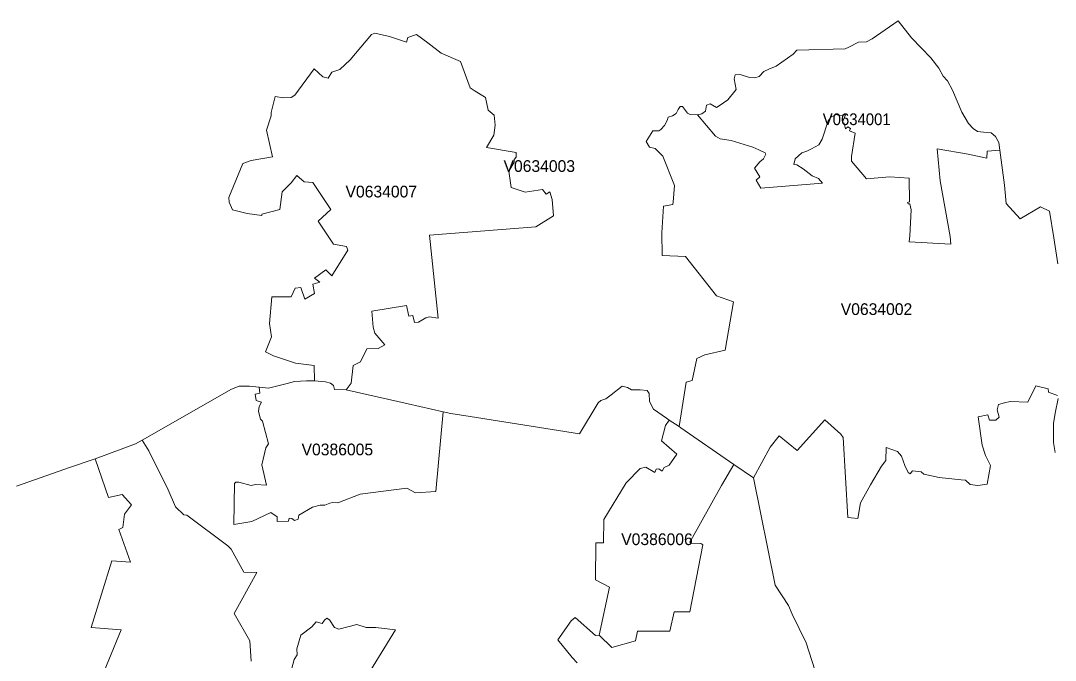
# Model space of a CAD drawing. Extents: x 369010 to 735936, y 6377141 to 6616555.
# Drawn here: x 440462 to 449282, y 6481136 to 6486588 of the extents above; entities that cross this region are included whole.
import ezdxf
from ezdxf.enums import TextEntityAlignment as Align

# ---------------------------------------------------------------- set-up
doc = ezdxf.new("R2010")
doc.units = 0
doc.header["$LTSCALE"] = 40
doc.layers.add('3', color=7, linetype='Continuous', lineweight=13)
doc.layers.add('4', color=7, linetype='Continuous')

msp = doc.modelspace()

# ---------------------------------------------------------------- linework, layer by layer
at = {"layer": '3'}
for points in [[(443297.34, 6483648.44), (443279.3, 6483498.16), (443236.1, 6483442.55), (443766.54, 6483322.39), (444063.79, 6483254.54), (444128.17, 6483239.81), (444294.33, 6483212.67), (445224.47, 6483065.7), (445385.67, 6483329.35), (445407.02, 6483350.36), (445451.37, 6483365.43), (445495.56, 6483399.02), (445590.23, 6483472.67), (445634.75, 6483462.41), (445670.33, 6483441.39), (445741.67, 6483442.72), (445803.4, 6483435.43), (445818.46, 6483409.45), (445823.92, 6483342.09), (445857.85, 6483275.89), (445966.59, 6483199.09), (445990.42, 6483183.37), (446074.33, 6483127.93), (446134.41, 6483507.26), (446186.04, 6483520.17), (446224.94, 6483709.34), (446293.46, 6483740.46), (446468.06, 6483779.19), (446537.41, 6484190.79), (446393.75, 6484241.27), (446129.77, 6484576.91), (445930.51, 6484587.34), (445927.2, 6484779.33), (445941.26, 6485008.05), (446020.71, 6485020.96), (446023.19, 6485040.16), (446034.77, 6485183.82), (445936.3, 6485432.24), (445869.77, 6485498.94), (445822.27, 6485509.2), (445794.13, 6485559.18), (445852.06, 6485649.55), (445900.88, 6485648.22), (445920.08, 6485659.81), (445950.86, 6485695.56), (445973.87, 6485736.6), (445982.81, 6485766.23), (446018.72, 6485776.49), (446049.5, 6485798.17), (446066.22, 6485831.6), (446082.77, 6485857.25), (446103.29, 6485855.93), (446146.82, 6485799.49), (446169.99, 6485787.91), (446231.39, 6485785.76), (446269.79, 6485793.53), (446299.25, 6485817.86), (446309.51, 6485866.52), (446338.97, 6485878.11), (446392.76, 6485848.65), (446417.25, 6485861.39), (446491.56, 6485912.7), (446562.4, 6486002.24), (446543.04, 6486091.94), (446552.14, 6486127.85), (446595.67, 6486130.5), (446676.43, 6486103.52), (446721.28, 6486101.04), (446757.2, 6486112.46), (446798.08, 6486156.15), (446840.45, 6486175.35), (446902.01, 6486199.68), (447047.99, 6486301.96), (447079.93, 6486336.55), (447491.37, 6486349.46), (447521.17, 6486361.05), (447604.58, 6486405.9), (447673.76, 6486408.55), (447719.94, 6486434.04), (447941.55, 6486587.95), (448055.41, 6486442.48), (448220.75, 6486272.01), (448289.93, 6486183.46), (448324.69, 6486114.78), (448361.93, 6486075.06), (448406.78, 6485995.62), (448484.89, 6485809.59), (448541.33, 6485710.95), (448582.54, 6485667.59), (448618.46, 6485643.09), (448670.92, 6485636.8), (448734.97, 6485631.67), (448770.89, 6485602.05), (448800.35, 6485549.58), (448808.12, 6485482.88), (448849.17, 6485186.47), (448862.24, 6485029.73), (448981.41, 6484898.99), (449156.18, 6485001.76), (449231.98, 6484964.53)], [(442965.34, 6483519.18), (443059.18, 6483509.08), (443104.36, 6483498.33), (443128.03, 6483477.64), (443135.81, 6483443.71), (443236.1, 6483442.55), (443279.3, 6483498.16), (443297.34, 6483648.44), (443357.91, 6483680.88), (443413.52, 6483789.61), (443508.02, 6483794.74), (443564.96, 6483824.53), (443482.04, 6483924.17), (443467.81, 6483974.65), (443454.24, 6484111.68), (443750.49, 6484159.68), (443769.85, 6484068.98), (443804.77, 6484075.44), (443819.01, 6484016.02), (443852.27, 6484017.35), (443915.66, 6484054.92), (443942.8, 6484062.69), (444020.42, 6484052.27), (443946.61, 6484760.96), (444853.24, 6484829.64), (445004.68, 6484924.14), (444992.93, 6485063.83), (444972.57, 6485128.54), (444941.45, 6485109.01), (444911.66, 6485147.9), (444762.88, 6485127.22), (444643.88, 6485167.27), (444623.19, 6485304.47), (444668.54, 6485380.93), (444668.54, 6485405.43), (444686.58, 6485423.63), (444686.58, 6485463.69), (444434.18, 6485508.37), (444496.25, 6485613.14), (444508, 6485697.38), (444497.57, 6485781.45), (444447.26, 6485825.97), (444423.92, 6485932.23), (444328.26, 6485991.64), (444294.5, 6486016.3), (444211.75, 6486240.23), (444047.73, 6486310.9), (443932.54, 6486400.11), (443836.88, 6486471.27), (443761.74, 6486445.45), (443751.48, 6486405.24), (443606.66, 6486451.91), (443479.89, 6486480.38), (443451.42, 6486471.27), (443270.2, 6486255.29), (443183.47, 6486172.37), (443114.95, 6486149.2), (443084, 6486097.4), (443038.65, 6486110.31), (442962.36, 6486176.35), (442797.85, 6485953.91), (442766.73, 6485934.54), (442702.02, 6485929.25), (442632.18, 6485941), (442597.75, 6485805.29), (442597.75, 6485776.82), (442556.38, 6485653.85), (442608.18, 6485426.12), (442425.79, 6485396.33), (442354.63, 6485370.51), (442236.46, 6485081.7), (442237.78, 6485041.48), (442268.9, 6484975.61), (442391.7, 6484944.5), (442517.15, 6484926.29), (442518.48, 6484938.04), (442669.91, 6484979.42), (442691.92, 6485128.71), (442768.22, 6485205), (442817.38, 6485269.71), (442879.44, 6485215.43), (442951.93, 6485207.65), (443105.85, 6484978.43), (442998.6, 6484880.12), (443128.36, 6484683.66), (443239.58, 6484662.98), (443251.33, 6484630.54), (443115.45, 6484414.39), (443063.65, 6484464.87), (442967.98, 6484392.38), (443013.17, 6484360.1), (442952.1, 6484342.06), (442966.33, 6484261.8), (442883.58, 6484213.96), (442849.98, 6484314.92), (442800.83, 6484308.47), (442768.55, 6484234.65), (442601.56, 6484233.33), (442582.69, 6484007.91), (442600.73, 6483892.72)], [(442795.03, 6483512.39), (442898.47, 6483518.85), (442965.34, 6483519.18), (442962.52, 6483648.6), (442805.96, 6483669.29), (442618.44, 6483731.35), (442550.25, 6483765.95), (442600.73, 6483892.72), (442582.69, 6484007.91), (442601.56, 6484233.33), (442768.55, 6484234.65), (442800.83, 6484308.47), (442849.98, 6484314.92), (442883.58, 6484213.96), (442966.33, 6484261.8), (442952.1, 6484342.06), (443013.17, 6484360.1), (442967.98, 6484392.38), (443063.65, 6484464.87), (443115.45, 6484414.39), (443251.33, 6484630.54), (443239.58, 6484662.98), (443128.36, 6484683.66), (442998.6, 6484880.12), (443105.85, 6484978.43), (442951.93, 6485207.65), (442879.44, 6485215.43), (442817.38, 6485269.71), (442768.22, 6485205), (442691.92, 6485128.71), (442669.91, 6484979.42), (442518.48, 6484938.04), (442517.15, 6484926.29), (442391.7, 6484944.5), (442268.9, 6484975.61), (442237.78, 6485041.48), (442236.46, 6485081.7), (442354.63, 6485370.51), (442425.79, 6485396.33), (442608.18, 6485426.12), (442556.38, 6485653.85), (442597.75, 6485776.82), (442597.75, 6485805.29), (442632.18, 6485941), (442702.02, 6485929.25), (442766.73, 6485934.54), (442797.85, 6485953.91), (442962.36, 6486176.35), (443038.65, 6486110.31), (443084, 6486097.4), (443114.95, 6486149.2), (443183.47, 6486172.37), (443270.2, 6486255.29), (443451.42, 6486471.27), (443479.89, 6486480.38), (443606.66, 6486451.91), (443751.48, 6486405.24), (443761.74, 6486445.45), (443836.88, 6486471.27), (443932.54, 6486400.11), (444047.73, 6486310.9), (444211.75, 6486240.23), (444294.5, 6486016.3), (444328.26, 6485991.64), (444423.92, 6485932.23), (444447.26, 6485825.97), (444497.57, 6485781.45), (444508, 6485697.38), (444496.25, 6485613.14), (444434.18, 6485508.37), (444686.58, 6485463.69), (444686.58, 6485423.63), (444668.54, 6485405.43), (444668.54, 6485380.93), (444623.19, 6485304.47), (444643.88, 6485167.27), (444762.88, 6485127.22), (444911.66, 6485147.9), (444941.45, 6485109.01), (444972.57, 6485128.54), (444992.93, 6485063.83), (445004.68, 6484924.14), (444853.24, 6484829.64), (443946.61, 6484760.96), (444020.42, 6484052.27), (443942.8, 6484062.69), (443915.66, 6484054.92), (443852.27, 6484017.35), (443819.01, 6484016.02), (443804.77, 6484075.44), (443769.85, 6484068.98), (443750.49, 6484159.68), (443454.24, 6484111.68), (443467.81, 6483974.65), (443482.04, 6483924.17), (443564.96, 6483824.53), (443508.02, 6483794.74), (443413.52, 6483789.61), (443357.91, 6483680.88), (443297.34, 6483648.44)], [(448042.67, 6485025.76), (448027.28, 6485025.76), (448022.15, 6485037.35), (448040.02, 6485043.8), (448034.89, 6485245.05), (447872.2, 6485256.64), (447673.43, 6485238.6), (447544.67, 6485390.04), (447545.99, 6485429.76), (447575.45, 6485629.85), (447526.79, 6485647.73), (447535.73, 6485669.57), (447512.72, 6485682.48), (447494.68, 6485667.09), (447481.94, 6485710.62), (447466.55, 6485723.53), (447492.2, 6485786.25), (447437.09, 6485779.8), (447417.89, 6485787.58), (447370.39, 6485767.05), (447346.06, 6485734.95), (447294.76, 6485577.22), (447265.3, 6485531.05), (447204.23, 6485496.46), (447164.5, 6485477.09), (447120.81, 6485461.7), (447064.54, 6485409.23), (447051.63, 6485363.06), (447077.28, 6485357.93), (447132.4, 6485325.82), (447210.68, 6485266.9), (447263.14, 6485243.73), (447297.73, 6485204.01), (446770.77, 6485161.64), (446731.05, 6485229.66), (446764.48, 6485257.96), (446716.98, 6485329.79), (446764.48, 6485384.91), (446795.26, 6485409.23), (446815.62, 6485448.96), (446809.33, 6485461.86), (446754.22, 6485487.52), (446702.91, 6485509.2), (446519.7, 6485566.96), (446426.03, 6485581.03), (446383.82, 6485603.7), (446231.39, 6485785.76), (446169.99, 6485787.91), (446146.82, 6485799.49), (446103.29, 6485855.93), (446082.77, 6485857.25), (446066.22, 6485831.6), (446049.5, 6485798.17), (446018.72, 6485776.49), (445982.81, 6485766.23), (445973.87, 6485736.6), (445950.86, 6485695.56), (445920.08, 6485659.81), (445900.88, 6485648.22), (445852.06, 6485649.55), (445794.13, 6485559.18), (445822.27, 6485509.2), (445869.77, 6485498.94), (445936.3, 6485432.24), (446034.77, 6485183.82), (446023.19, 6485040.16), (446020.71, 6485020.96), (445941.26, 6485008.05), (445927.2, 6484779.33), (445930.51, 6484587.34), (446129.77, 6484576.91), (446393.75, 6484241.27), (446537.41, 6484190.79), (446468.06, 6483779.19), (446293.46, 6483740.46), (446224.94, 6483709.34), (446186.04, 6483520.17), (446134.41, 6483507.26), (446074.33, 6483127.93)], [(449304.8, 6484516.51), (449268.56, 6484736.3), (449231.98, 6484964.53), (449156.18, 6485001.76), (448981.41, 6484898.99), (448862.24, 6485029.73), (448849.17, 6485186.47), (448808.12, 6485482.88), (448701.71, 6485475.11), (448699.06, 6485417.51), (448539.18, 6485451.11), (448273.88, 6485495.96), (448284.14, 6485403.61), (448300.85, 6485221.55), (448384.43, 6484747.22), (448390.23, 6484682.84), (448037.21, 6484702.2), (448041.01, 6484753.01), (448052.93, 6484974.46), (448042.67, 6485025.76)], [(449231.98, 6484964.53), (449268.56, 6484736.3), (449304.8, 6484516.51)], [(442600.73, 6483892.72), (442550.25, 6483765.95), (442618.44, 6483731.35), (442805.96, 6483669.29), (442962.52, 6483648.6), (442965.34, 6483519.18)], [(440425.02, 6482620.16), (440885.78, 6482782.52), (441078.76, 6482846.74), (441096.13, 6482853.19), (441441.38, 6482981.62), (441497.65, 6483013.56), (442259.79, 6483448.18), (442323.02, 6483473.33), (442412.06, 6483472.34), (442493.82, 6483464.23), (442575.24, 6483456.29), (442733.47, 6483495.35), (442795.03, 6483512.39)], [(445207.09, 6481114.9), (445164.39, 6481158.93), (445040.09, 6481310.2), (445155.12, 6481472.06), (445190.04, 6481500.53), (445363.49, 6481346.44), (445394.27, 6481349.09), (445482.65, 6481758.22), (445362.33, 6481822.93), (445365.97, 6482136.72), (445429.36, 6482136.72), (445434.49, 6482334.67), (445622.67, 6482649.46), (445741.67, 6482771.1), (445790.82, 6482781.53), (445868.44, 6482737.5), (445880.19, 6482765.97), (445900.88, 6482768.62), (445929.35, 6482747.93), (445947.39, 6482778.88), (445991.41, 6482799.57), (446056.12, 6482894.07), (445924.55, 6483006.94), (445959.47, 6483136.37), (445990.42, 6483183.37), (445966.59, 6483199.09), (445857.85, 6483275.89), (445823.92, 6483342.09), (445818.46, 6483409.45), (445803.4, 6483435.43), (445741.67, 6483442.72), (445670.33, 6483441.39), (445634.75, 6483462.41), (445590.23, 6483472.67), (445495.56, 6483399.02), (445451.37, 6483365.43), (445407.02, 6483350.36), (445385.67, 6483329.35), (445224.47, 6483065.7), (444294.33, 6483212.67), (444128.17, 6483239.81), (444063.79, 6483254.54), (444063.62, 6483254.54), (444000.4, 6482574.81), (443827.12, 6482564.39), (443754.63, 6482603.28), (443356.75, 6482552.97), (443164.11, 6482477.83), (443123.89, 6482481.8), (443096.75, 6482474.02), (443054.05, 6482458.46), (443015.32, 6482457.14), (442948.95, 6482440.59), (442833.76, 6482373.23), (442825.98, 6482339.63), (442796.36, 6482328.05), (442773.02, 6482344.76), (442749.68, 6482346.09), (442745.88, 6482321.43), (442648.89, 6482317.62), (442648.89, 6482359), (442594.44, 6482395.24), (442432.58, 6482317.79), (442278.66, 6482294.45), (442285.12, 6482642.67), (442295.71, 6482654.59), (442320.37, 6482654.59), (442427.78, 6482624.8), (442463.86, 6482635.06), (442558.36, 6482627.28), (442518.31, 6482803.37), (442552.74, 6482947.03), (442574.75, 6482981.95), (442522.94, 6483173.44), (442506.06, 6483191.65), (442489.68, 6483255.53), (442493.48, 6483298.23), (442515.5, 6483335.63), (442470.15, 6483351.19), (442459.89, 6483404.32), (442501.26, 6483413.42), (442493.82, 6483464.23), (442412.06, 6483472.34), (442323.02, 6483473.33), (442259.79, 6483448.18), (441497.65, 6483013.56)], [(446074.33, 6483127.93), (446090.05, 6483117.5), (446541.88, 6482805.69), (446708.21, 6482690.83), (446852.2, 6482951.5), (446928.66, 6483048.49), (447081.26, 6482925.52), (447315.94, 6483186.35), (447453.14, 6483063.38), (447472.51, 6483033.59), (447513.88, 6482353.53), (447599.28, 6482344.43), (447619.97, 6482477.66), (447707.85, 6482631.75), (447801.53, 6482789.47), (447836.45, 6482838.63), (447840.26, 6482948.69), (447936.08, 6482915.09), (447972.16, 6482876.2), (447998.15, 6482795.93), (448029.1, 6482737.67), (448045.98, 6482724.76), (448065.34, 6482751.9), (448139.16, 6482741.64), (448161.17, 6482722.28), (448293.08, 6482693.64), (448479.1, 6482675.11), (448515.35, 6482672.63), (448556.72, 6482635.06), (448622.76, 6482624.63), (448701.71, 6482636.38), (448730.17, 6482796.75), (448685.82, 6482881.82), (448657.35, 6482969.71), (448623.59, 6483210.51), (448707.66, 6483227.4), (448721.9, 6483182.05), (448776.35, 6483183.37), (448802.17, 6483207.87), (448785.28, 6483271.42), (448797.04, 6483316.6), (448850, 6483329.68), (448896.83, 6483340.93), (449046.78, 6483335.8), (449116.62, 6483476.64), (449219.9, 6483450), (449225.03, 6483421.53), (449300, 6483394.39)], [(449300, 6483394.39), (449225.03, 6483421.53), (449219.9, 6483450), (449116.62, 6483476.64), (449046.78, 6483335.8), (448896.83, 6483340.93), (448850, 6483329.68), (448797.04, 6483316.6), (448785.28, 6483271.42), (448802.17, 6483207.87), (448776.35, 6483183.37), (448721.9, 6483182.05), (448707.66, 6483227.4), (448623.59, 6483210.51), (448657.35, 6482969.71), (448685.82, 6482881.82), (448730.17, 6482796.75), (448701.71, 6482636.38), (448622.76, 6482624.63), (448556.72, 6482635.06), (448515.35, 6482672.63), (448479.1, 6482675.11), (448293.08, 6482693.64), (448161.17, 6482722.28), (448139.16, 6482741.64), (448065.34, 6482751.9), (448045.98, 6482724.76), (448029.1, 6482737.67), (447998.15, 6482795.93), (447972.16, 6482876.2), (447936.08, 6482915.09), (447840.26, 6482948.69), (447836.45, 6482838.63), (447801.53, 6482789.47), (447707.85, 6482631.75), (447619.97, 6482477.66), (447599.28, 6482344.43), (447513.88, 6482353.53), (447472.51, 6483033.59), (447453.14, 6483063.38), (447315.94, 6483186.35), (447081.26, 6482925.52), (446928.66, 6483048.49), (446852.2, 6482951.5), (446708.21, 6482690.83), (446892.91, 6481775.1), (447006.78, 6481602.48), (447040.21, 6481527.83), (447159.21, 6481284.05), (447233.02, 6481055.82)], [(449307.78, 6483367.25), (449281.96, 6483242.95), (449265.41, 6483155.07), (449266.74, 6482993.37), (449282.29, 6482906.65)], [(449282.29, 6482906.65), (449266.74, 6482993.37), (449265.41, 6483155.07), (449281.96, 6483242.95), (449307.78, 6483367.25)], [(441497.65, 6483013.56), (441441.38, 6482981.62), (441096.13, 6482853.19), (441209.34, 6482522.35), (441326.68, 6482548.5), (441406.12, 6482462.44), (441345.55, 6482380.35), (441332.47, 6482266.98), (441299.87, 6482251.25), (441399.34, 6481972.54), (441237.64, 6481984.29), (441063.7, 6481415.46), (441318.74, 6481395.43), (440873.53, 6480310.72), (440728.38, 6480457.85), (440203.9, 6480028.87)], [(441497.65, 6483013.56), (441554.75, 6482921.21), (441720.42, 6482589.54), (441781.49, 6482443.07), (441853.32, 6482375.22), (441878.14, 6482373.89), (442227.35, 6482110.91), (442257.31, 6482082.11), (442364.39, 6481886.32), (442473.96, 6481883.67), (442280.81, 6481535.94), (442416.53, 6481300.93), (442427.61, 6481128.31)], [(442427.61, 6481128.31), (442416.53, 6481300.93), (442280.81, 6481535.94), (442473.96, 6481883.67), (442364.39, 6481886.32), (442257.31, 6482082.11), (442227.35, 6482110.91), (441878.14, 6482373.89), (441853.32, 6482375.22), (441781.49, 6482443.07), (441720.42, 6482589.54), (441554.75, 6482921.21), (441497.65, 6483013.56)], [(440203.9, 6480028.87), (440728.38, 6480457.85), (440873.53, 6480310.72), (441318.74, 6481395.43), (441063.7, 6481415.46), (441237.64, 6481984.29), (441399.34, 6481972.54), (441299.87, 6482251.25), (441332.47, 6482266.98), (441345.55, 6482380.35), (441406.12, 6482462.44), (441326.68, 6482548.5), (441209.34, 6482522.35), (441096.13, 6482853.19), (441078.76, 6482846.74), (440885.78, 6482782.52), (440425.02, 6482620.16)], [(446541.88, 6482805.69), (446437.11, 6482625.62), (446174.29, 6482158.4), (446166.02, 6482142.68), (446176.28, 6482133.74), (446260.52, 6482131.1), (446275.91, 6482120.67), (446165.19, 6481550.18), (446031.96, 6481548.85), (445994.56, 6481384.51), (445721.64, 6481383.18), (445701.95, 6481302.09), (445502.84, 6481245.15), (445394.27, 6481349.09), (445363.49, 6481346.44), (445190.04, 6481500.53), (445155.12, 6481472.06), (445040.09, 6481310.2), (445164.39, 6481158.93), (445207.09, 6481114.9)], [(447233.02, 6481055.82), (447159.21, 6481284.05), (447040.21, 6481527.83), (447006.78, 6481602.48), (446892.91, 6481775.1), (446708.21, 6482690.83), (446541.88, 6482805.69)], [(443389.19, 6480961.81), (443657.64, 6481396.26), (443490.65, 6481415.79), (443408.39, 6481415.79), (443326.3, 6481440.61), (443175.2, 6481402.38), (443137.3, 6481414.13), (443095.59, 6481479.34), (443070.76, 6481493.74), (443051.23, 6481478.02), (443032.86, 6481449.39), (442982.05, 6481463.78), (442942.99, 6481420.59), (442848.99, 6481348.76), (442816.22, 6481232.41), (442817.54, 6481181.43), (442792.72, 6481142.38), (442710.46, 6480832.88)], [(442710.46, 6480832.88), (442792.72, 6481142.38), (442817.54, 6481181.43), (442816.22, 6481232.41), (442848.99, 6481348.76), (442942.99, 6481420.59), (442982.05, 6481463.78), (443032.86, 6481449.39), (443051.23, 6481478.02), (443070.76, 6481493.74), (443095.59, 6481479.34), (443137.3, 6481414.13), (443175.2, 6481402.38), (443326.3, 6481440.61), (443408.39, 6481415.79), (443490.65, 6481415.79), (443657.64, 6481396.26), (443389.19, 6480961.81)]]:
    msp.add_lwpolyline(points, dxfattribs=at)
for points in [[(446231.39, 6485785.76), (446383.82, 6485603.7), (446426.03, 6485581.03), (446519.7, 6485566.96), (446702.91, 6485509.2), (446754.22, 6485487.52), (446809.33, 6485461.86), (446815.62, 6485448.96), (446795.26, 6485409.23), (446764.48, 6485384.91), (446716.98, 6485329.79), (446764.48, 6485257.96), (446731.05, 6485229.66), (446770.77, 6485161.64), (447297.73, 6485204.01), (447263.14, 6485243.73), (447210.68, 6485266.9), (447132.4, 6485325.82), (447077.28, 6485357.93), (447051.63, 6485363.06), (447064.54, 6485409.23), (447120.81, 6485461.7), (447164.5, 6485477.09), (447204.23, 6485496.46), (447265.3, 6485531.05), (447294.76, 6485577.22), (447346.06, 6485734.95), (447370.39, 6485767.05), (447417.89, 6485787.58), (447437.09, 6485779.8), (447492.2, 6485786.25), (447466.55, 6485723.53), (447481.94, 6485710.62), (447494.68, 6485667.09), (447512.72, 6485682.48), (447535.73, 6485669.57), (447526.79, 6485647.73), (447575.45, 6485629.85), (447545.99, 6485429.76), (447544.67, 6485390.04), (447673.43, 6485238.6), (447872.2, 6485256.64), (448034.89, 6485245.05), (448040.02, 6485043.8), (448022.15, 6485037.35), (448027.28, 6485025.76), (448042.67, 6485025.76), (448052.93, 6484974.46), (448041.01, 6484753.01), (448037.21, 6484702.2), (448390.23, 6484682.84), (448384.43, 6484747.22), (448300.85, 6485221.55), (448284.14, 6485403.61), (448273.88, 6485495.96), (448539.18, 6485451.11), (448699.06, 6485417.51), (448701.71, 6485475.11), (448808.12, 6485482.88), (448800.35, 6485549.58), (448770.89, 6485602.05), (448734.97, 6485631.67), (448670.92, 6485636.8), (448618.46, 6485643.09), (448582.54, 6485667.59), (448541.33, 6485710.95), (448484.89, 6485809.59), (448406.78, 6485995.62), (448361.93, 6486075.06), (448324.69, 6486114.78), (448289.93, 6486183.46), (448220.75, 6486272.01), (448055.41, 6486442.48), (447941.55, 6486587.95), (447719.94, 6486434.04), (447673.76, 6486408.55), (447604.58, 6486405.9), (447521.17, 6486361.05), (447491.37, 6486349.46), (447079.93, 6486336.55), (447047.99, 6486301.96), (446902.01, 6486199.68), (446840.45, 6486175.35), (446798.08, 6486156.15), (446757.2, 6486112.46), (446721.28, 6486101.04), (446676.43, 6486103.52), (446595.67, 6486130.5), (446552.14, 6486127.85), (446543.04, 6486091.94), (446562.4, 6486002.24), (446491.56, 6485912.7), (446417.25, 6485861.39), (446392.76, 6485848.65), (446338.97, 6485878.11), (446309.51, 6485866.52), (446299.25, 6485817.86), (446269.79, 6485793.53)], [(442965.34, 6483519.18), (442898.47, 6483518.85), (442795.03, 6483512.39), (442733.47, 6483495.35), (442575.24, 6483456.29), (442493.82, 6483464.23), (442501.26, 6483413.42), (442459.89, 6483404.32), (442470.15, 6483351.19), (442515.5, 6483335.63), (442493.48, 6483298.23), (442489.68, 6483255.53), (442506.06, 6483191.65), (442522.94, 6483173.44), (442574.75, 6482981.95), (442552.74, 6482947.03), (442518.31, 6482803.37), (442558.36, 6482627.28), (442463.86, 6482635.06), (442427.78, 6482624.8), (442320.37, 6482654.59), (442295.71, 6482654.59), (442285.12, 6482642.67), (442278.66, 6482294.45), (442432.58, 6482317.79), (442594.44, 6482395.24), (442648.89, 6482359), (442648.89, 6482317.62), (442745.88, 6482321.43), (442749.68, 6482346.09), (442773.02, 6482344.76), (442796.36, 6482328.05), (442825.98, 6482339.63), (442833.76, 6482373.23), (442948.95, 6482440.59), (443015.32, 6482457.14), (443054.05, 6482458.46), (443096.75, 6482474.02), (443123.89, 6482481.8), (443164.11, 6482477.83), (443356.75, 6482552.97), (443754.63, 6482603.28), (443827.12, 6482564.39), (444000.4, 6482574.81), (444063.62, 6483254.54), (444063.79, 6483254.54), (443766.54, 6483322.39), (443236.1, 6483442.55), (443135.81, 6483443.71), (443128.03, 6483477.64), (443104.36, 6483498.33), (443059.18, 6483509.08)], [(445990.42, 6483183.37), (445959.47, 6483136.37), (445924.55, 6483006.94), (446056.12, 6482894.07), (445991.41, 6482799.57), (445947.39, 6482778.88), (445929.35, 6482747.93), (445900.88, 6482768.62), (445880.19, 6482765.97), (445868.44, 6482737.5), (445790.82, 6482781.53), (445741.67, 6482771.1), (445622.67, 6482649.46), (445434.49, 6482334.67), (445429.36, 6482136.72), (445365.97, 6482136.72), (445362.33, 6481822.93), (445482.65, 6481758.22), (445394.27, 6481349.09), (445502.84, 6481245.15), (445701.95, 6481302.09), (445721.64, 6481383.18), (445994.56, 6481384.51), (446031.96, 6481548.85), (446165.19, 6481550.18), (446275.91, 6482120.67), (446260.52, 6482131.1), (446176.28, 6482133.74), (446166.02, 6482142.68), (446174.29, 6482158.4), (446437.11, 6482625.62), (446541.88, 6482805.69), (446090.05, 6483117.5), (446074.33, 6483127.93)]]:
    msp.add_lwpolyline(points, close=True, dxfattribs=at)

# ---------------------------------------------------------------- texts
at = {"layer": '4', "width": 0.95}
msp.add_text('V0634001', height=100, dxfattribs=at).set_placement((447589.02, 6485697.78), align=Align.CENTER)
at = {"layer": '4'}
for s, p in [('V0634003', (444882.8, 6485298.85)), ('V0634007', (443535.92, 6485081.35)), ('V0634002', (447757.72, 6484079.23)), ('V0386005', (443161.25, 6482883.04)), ('V0386006', (445886.21, 6482117.84))]:
    msp.add_text(s, height=100, dxfattribs=at).set_placement(p, align=Align.CENTER)

doc.saveas('drawing.dxf')
